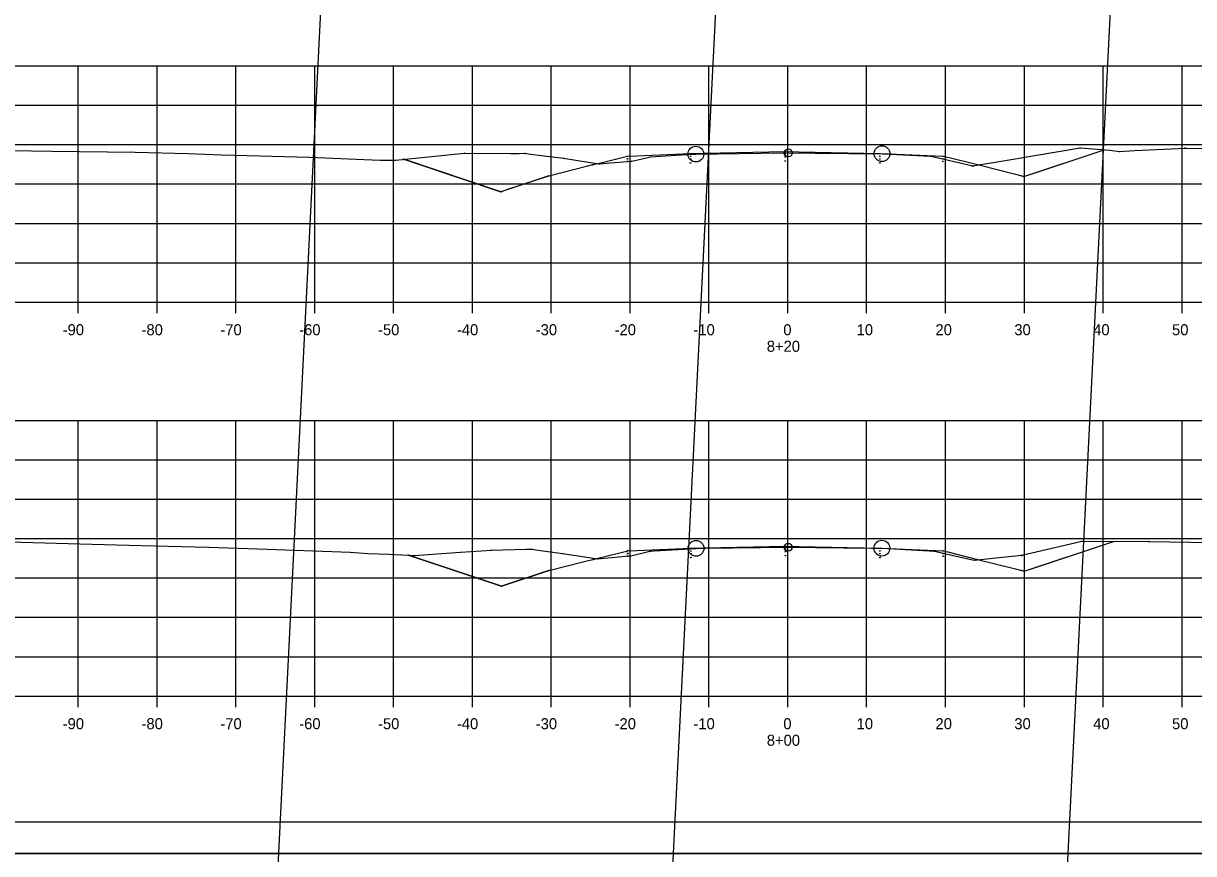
# Model space of a CAD drawing. Extents: x 1300404 to 1323571, y 234004 to 252077.
# Drawn here: x 1315620.3 to 1315768.7, y 242768.5 to 242873.8 of the extents above; entities that cross this region are included whole.
import ezdxf

# ---------------------------------------------------------------- set-up
doc = ezdxf.new("R2010")
doc.units = 0
for name, color, linetype in [('Default', 7, 'Continuous'), ('R_Axis', 7, 'Continuous'), ('R_Axis Annot', 7, 'Continuous'), ('R_Draft', 7, 'Continuous'), ('R_Exist Surface', 7, 'Continuous'), ('R_Fin Surface', 7, 'Continuous'), ('R_Floodway', 7, 'Continuous'), ('R_Grid', 7, 'Continuous'), ('R_No Plot', 7, 'Continuous')]:
    doc.layers.add(name, color=color, linetype=linetype)

msp = doc.modelspace()

# ---------------------------------------------------------------- linework, layer by layer
at = {"layer": 'Default'}
msp.add_line((1315875.46, 242772.46), (1315559.28, 242772.46), dxfattribs=at)
at = {"layer": 'R_Axis'}
for p, q in [((1315577.28, 242838.46), (1315857.28, 242838.46)), ((1315627.28, 242837.06), (1315627.28, 242838.46)), ((1315637.28, 242837.06), (1315637.28, 242838.46)), ((1315647.28, 242837.06), (1315647.28, 242838.46)), ((1315657.28, 242837.06), (1315657.28, 242838.46)), ((1315667.28, 242837.06), (1315667.28, 242838.46)), ((1315677.28, 242837.06), (1315677.28, 242838.46)), ((1315687.28, 242837.06), (1315687.28, 242838.46)), ((1315697.28, 242837.06), (1315697.28, 242838.46)), ((1315707.28, 242837.06), (1315707.28, 242838.46)), ((1315717.28, 242837.06), (1315717.28, 242838.46)), ((1315727.28, 242837.06), (1315727.28, 242838.46)), ((1315737.28, 242837.06), (1315737.28, 242838.46)), ((1315747.28, 242837.06), (1315747.28, 242838.46)), ((1315757.28, 242837.06), (1315757.28, 242838.46)), ((1315767.28, 242837.06), (1315767.28, 242838.46)), ((1315577.28, 242788.46), (1315857.28, 242788.46)), ((1315627.28, 242787.06), (1315627.28, 242788.46)), ((1315637.28, 242787.06), (1315637.28, 242788.46)), ((1315647.28, 242787.06), (1315647.28, 242788.46)), ((1315657.28, 242787.06), (1315657.28, 242788.46)), ((1315667.28, 242787.06), (1315667.28, 242788.46)), ((1315677.28, 242787.06), (1315677.28, 242788.46)), ((1315687.28, 242787.06), (1315687.28, 242788.46)), ((1315697.28, 242787.06), (1315697.28, 242788.46)), ((1315707.28, 242787.06), (1315707.28, 242788.46)), ((1315717.28, 242787.06), (1315717.28, 242788.46)), ((1315727.28, 242787.06), (1315727.28, 242788.46)), ((1315737.28, 242787.06), (1315737.28, 242788.46)), ((1315747.28, 242787.06), (1315747.28, 242788.46)), ((1315757.28, 242787.06), (1315757.28, 242788.46)), ((1315767.28, 242787.06), (1315767.28, 242788.46))]:
    msp.add_line(p, q, dxfattribs=at)
at = {"layer": 'R_Draft'}
for points in [[(1315754.35, 242858.09), (1315754.4, 242857.99), (1315754.3, 242857.99)], [(1315757.4, 242857.85), (1315757.45, 242857.75), (1315757.35, 242857.75)], [(1315757.4, 242857.85), (1315757.45, 242857.75), (1315757.35, 242857.75)], [(1315767.7, 242858.07), (1315767.75, 242857.97), (1315767.65, 242857.97)], [(1315667.52, 242856.53), (1315667.57, 242856.43), (1315667.47, 242856.43)], [(1315668.56, 242856.64), (1315668.61, 242856.54), (1315668.51, 242856.54)], [(1315668.56, 242856.64), (1315668.61, 242856.54), (1315668.51, 242856.54)], [(1315676.29, 242857.41), (1315676.34, 242857.31), (1315676.24, 242857.31)], [(1315683.92, 242857.4), (1315683.97, 242857.3), (1315683.87, 242857.3)], [(1315688.85, 242856.79), (1315688.9, 242856.69), (1315688.8, 242856.69)], [(1315696.95, 242857.05), (1315697, 242856.95), (1315696.9, 242856.95)], [(1315696.95, 242856.72), (1315697, 242856.62), (1315696.9, 242856.62)], [(1315696.95, 242856.39), (1315697, 242856.29), (1315696.9, 242856.29)], [(1315697.48, 242856.4), (1315697.53, 242856.3), (1315697.43, 242856.3)], [(1315699.86, 242856.96), (1315699.91, 242856.86), (1315699.81, 242856.86)], [(1315704.95, 242857.37), (1315705, 242857.27), (1315704.9, 242857.27)], [(1315704.95, 242857.04), (1315705, 242856.94), (1315704.9, 242856.94)], [(1315704.95, 242856.71), (1315705, 242856.61), (1315704.9, 242856.61)], [(1315716.95, 242857.61), (1315717, 242857.51), (1315716.9, 242857.51)], [(1315716.95, 242857.28), (1315717, 242857.18), (1315716.9, 242857.18)], [(1315716.95, 242856.95), (1315717, 242856.85), (1315716.9, 242856.85)], [(1315716.95, 242856.45), (1315717, 242856.35), (1315716.9, 242856.35)], [(1315728.95, 242857.37), (1315729, 242857.27), (1315728.9, 242857.27)], [(1315728.95, 242857.04), (1315729, 242856.94), (1315728.9, 242856.94)], [(1315728.95, 242856.71), (1315729, 242856.61), (1315728.9, 242856.61)], [(1315735.38, 242857.04), (1315735.43, 242856.94), (1315735.33, 242856.94)], [(1315736.95, 242857.05), (1315737, 242856.95), (1315736.9, 242856.95)], [(1315736.95, 242856.72), (1315737, 242856.62), (1315736.9, 242856.62)], [(1315736.95, 242856.39), (1315737, 242856.29), (1315736.9, 242856.29)], [(1315759.35, 242857.65), (1315759.4, 242857.55), (1315759.3, 242857.55)], [(1315692.57, 242855.96), (1315692.62, 242855.86), (1315692.52, 242855.86)], [(1315693.38, 242856.07), (1315693.43, 242855.97), (1315693.33, 242855.97)], [(1315704.95, 242856.21), (1315705, 242856.11), (1315704.9, 242856.11)], [(1315728.95, 242856.21), (1315729, 242856.11), (1315728.9, 242856.11)], [(1315740.76, 242855.79), (1315740.81, 242855.69), (1315740.71, 242855.69)], [(1315741.33, 242855.96), (1315741.38, 242855.86), (1315741.28, 242855.86)], [(1315686.95, 242854.55), (1315687, 242854.45), (1315686.9, 242854.45)], [(1315746.95, 242854.55), (1315747, 242854.45), (1315746.9, 242854.45)], [(1315747.23, 242854.46), (1315747.28, 242854.36), (1315747.18, 242854.36)], [(1315680.88, 242852.53), (1315680.93, 242852.43), (1315680.83, 242852.43)], [(1315716.97, 242807.53), (1315717.02, 242807.43), (1315716.92, 242807.43)], [(1315754.58, 242808.18), (1315754.63, 242808.08), (1315754.53, 242808.08)], [(1315758.47, 242808.11), (1315758.52, 242808.01), (1315758.42, 242808.01)], [(1315758.47, 242808.11), (1315758.52, 242808.01), (1315758.42, 242808.01)], [(1315763.05, 242808.13), (1315763.1, 242808.03), (1315763, 242808.03)], [(1315669.15, 242806.41), (1315669.2, 242806.31), (1315669.1, 242806.31)], [(1315669.15, 242806.41), (1315669.2, 242806.31), (1315669.1, 242806.31)], [(1315669.91, 242806.35), (1315669.96, 242806.25), (1315669.86, 242806.25)], [(1315679.7, 242807.05), (1315679.75, 242806.95), (1315679.65, 242806.95)], [(1315684.75, 242807.16), (1315684.8, 242807.06), (1315684.7, 242807.06)], [(1315688.7, 242806.6), (1315688.75, 242806.5), (1315688.65, 242806.5)], [(1315692.59, 242805.87), (1315692.64, 242805.77), (1315692.54, 242805.77)], [(1315693.13, 242805.94), (1315693.18, 242805.84), (1315693.08, 242805.84)], [(1315696.97, 242806.97), (1315697.02, 242806.87), (1315696.92, 242806.87)], [(1315696.97, 242806.63), (1315697.02, 242806.53), (1315696.92, 242806.53)], [(1315696.97, 242806.3), (1315697.02, 242806.2), (1315696.92, 242806.2)], [(1315697.36, 242806.31), (1315697.41, 242806.21), (1315697.31, 242806.21)], [(1315699.82, 242806.91), (1315699.87, 242806.81), (1315699.77, 242806.81)], [(1315704.97, 242807.29), (1315705.02, 242807.19), (1315704.92, 242807.19)], [(1315704.97, 242806.95), (1315705.02, 242806.85), (1315704.92, 242806.85)], [(1315704.97, 242806.62), (1315705.02, 242806.52), (1315704.92, 242806.52)], [(1315704.97, 242806.12), (1315705.02, 242806.02), (1315704.92, 242806.02)], [(1315716.97, 242807.19), (1315717.02, 242807.09), (1315716.92, 242807.09)], [(1315716.97, 242806.86), (1315717.02, 242806.76), (1315716.92, 242806.76)], [(1315716.97, 242806.36), (1315717.02, 242806.26), (1315716.92, 242806.26)], [(1315728.97, 242807.29), (1315729.02, 242807.19), (1315728.92, 242807.19)], [(1315728.97, 242806.95), (1315729.02, 242806.85), (1315728.92, 242806.85)], [(1315728.97, 242806.62), (1315729.02, 242806.52), (1315728.92, 242806.52)], [(1315728.97, 242806.12), (1315729.02, 242806.02), (1315728.92, 242806.02)], [(1315735.87, 242806.92), (1315735.92, 242806.82), (1315735.82, 242806.82)], [(1315736.97, 242806.97), (1315737.02, 242806.87), (1315736.92, 242806.87)], [(1315736.97, 242806.63), (1315737.02, 242806.53), (1315736.92, 242806.53)], [(1315736.97, 242806.3), (1315737.02, 242806.2), (1315736.92, 242806.2)], [(1315741.34, 242805.87), (1315741.39, 242805.77), (1315741.29, 242805.77)], [(1315746.94, 242806.38), (1315746.99, 242806.28), (1315746.89, 242806.28)], [(1315686.97, 242804.47), (1315687.02, 242804.37), (1315686.92, 242804.37)], [(1315740.95, 242805.77), (1315741, 242805.67), (1315740.9, 242805.67)], [(1315746.97, 242804.47), (1315747.02, 242804.37), (1315746.92, 242804.37)], [(1315747.25, 242804.37), (1315747.3, 242804.27), (1315747.2, 242804.27)], [(1315680.98, 242802.47), (1315681.03, 242802.37), (1315680.93, 242802.37)]]:
    msp.add_lwpolyline(points, close=True, dxfattribs=at)
at = {"layer": 'R_Exist Surface'}
for points in [[(1315613.53, 242857.78), (1315623.94, 242857.62), (1315634.52, 242857.51), (1315641.22, 242857.32), (1315645.46, 242857.17), (1315656.64, 242856.87), (1315663.51, 242856.55), (1315665.61, 242856.47), (1315667.52, 242856.48), (1315675.43, 242857.3), (1315676.29, 242857.36), (1315682.09, 242857.34), (1315683.2, 242857.34), (1315683.92, 242857.35), (1315684.63, 242857.25), (1315688.85, 242856.74), (1315691.96, 242856.24), (1315693.38, 242856.02), (1315694.8, 242856.14), (1315697.48, 242856.35), (1315698.24, 242856.53), (1315699.86, 242856.91), (1315703.78, 242857.14), (1315705.61, 242857.25), (1315713.9, 242857.36), (1315717.33, 242857.4), (1315720.76, 242857.37), (1315729.23, 242857.3), (1315731.12, 242857.2), (1315735.38, 242856.99), (1315737.1, 242856.59), (1315740.76, 242855.74), (1315745.61, 242856.57), (1315754.35, 242858.04), (1315758.11, 242857.73), (1315759.35, 242857.6), (1315761.29, 242857.69), (1315767.7, 242858.02), (1315774.57, 242857.98)], [(1315617.04, 242808.07), (1315627.49, 242807.79), (1315635.25, 242807.59), (1315643.84, 242807.36), (1315651.26, 242807.09), (1315661.78, 242806.72), (1315664, 242806.54), (1315666.69, 242806.48), (1315669.91, 242806.3), (1315675.77, 242806.71), (1315679.7, 242807), (1315684.07, 242807.1), (1315684.75, 242807.11), (1315685.62, 242807), (1315688.7, 242806.55), (1315691.25, 242806.16), (1315693.13, 242805.89), (1315696.7, 242806.21), (1315697.36, 242806.26), (1315699.61, 242806.81), (1315699.82, 242806.86), (1315700.32, 242806.89), (1315705.64, 242807.21), (1315706.84, 242807.23), (1315717.32, 242807.35), (1315727.86, 242807.25), (1315729.21, 242807.24), (1315735.19, 242806.91), (1315735.87, 242806.87), (1315740.51, 242805.82), (1315740.95, 242805.72), (1315743.3, 242805.96), (1315746.94, 242806.33), (1315751.88, 242807.5), (1315754.58, 242808.13), (1315754.85, 242808.1), (1315755.67, 242808.13), (1315763.05, 242808.08), (1315779.03, 242807.85)]]:
    msp.add_lwpolyline(points, dxfattribs=at)
at = {"layer": 'R_Fin Surface'}
for points in [[(1315668.56, 242856.59), (1315670.42, 242855.97), (1315680.88, 242852.48), (1315681.78, 242852.78), (1315686.95, 242854.5), (1315691.75, 242855.7), (1315692.57, 242855.91), (1315693.21, 242856.07), (1315696.95, 242857), (1315698.12, 242857.05), (1315704.95, 242857.32), (1315706.69, 242857.36), (1315716.95, 242857.56), (1315718.68, 242857.53), (1315728.95, 242857.32), (1315730.09, 242857.28), (1315736.95, 242857), (1315737.57, 242856.85), (1315741.33, 242855.91), (1315746.15, 242854.7), (1315746.95, 242854.5), (1315746.99, 242854.49), (1315747.23, 242854.41), (1315748.67, 242854.89), (1315757.4, 242857.8)], [(1315669.15, 242806.36), (1315670.94, 242805.77), (1315680.98, 242802.42), (1315681.87, 242802.72), (1315686.97, 242804.42), (1315691.77, 242805.62), (1315692.59, 242805.82), (1315693.23, 242805.98), (1315696.97, 242806.92), (1315698.13, 242806.96), (1315704.97, 242807.24), (1315706.71, 242807.27), (1315716.97, 242807.48), (1315718.7, 242807.44), (1315728.97, 242807.24), (1315730.11, 242807.19), (1315736.97, 242806.92), (1315737.59, 242806.76), (1315741.34, 242805.82), (1315746.17, 242804.62), (1315746.97, 242804.42), (1315747.01, 242804.4), (1315747.25, 242804.32), (1315748.7, 242804.8), (1315758.47, 242808.06)]]:
    msp.add_lwpolyline(points, dxfattribs=at)
at = {"layer": 'R_Floodway'}
for p, q in [((1315724.08, 242194.52), (1315766.53, 243041.85)), ((1315673.23, 242178.64), (1315715.45, 243021.54)), ((1315622.37, 242162.75), (1315664.37, 243001.24))]:
    msp.add_line(p, q, dxfattribs=at)
at = {"layer": 'R_Grid'}
for p, q in [((1315577.28, 242868.46), (1315857.28, 242868.46)), ((1315627.28, 242838.46), (1315627.28, 242868.46)), ((1315637.28, 242838.46), (1315637.28, 242868.46)), ((1315647.28, 242838.46), (1315647.28, 242868.46)), ((1315657.28, 242838.46), (1315657.28, 242868.46)), ((1315667.28, 242838.46), (1315667.28, 242868.46)), ((1315677.28, 242838.46), (1315677.28, 242868.46)), ((1315687.28, 242838.46), (1315687.28, 242868.46)), ((1315697.28, 242838.46), (1315697.28, 242868.46)), ((1315707.28, 242838.46), (1315707.28, 242868.46)), ((1315717.28, 242838.46), (1315717.28, 242868.46)), ((1315727.28, 242838.46), (1315727.28, 242868.46)), ((1315737.28, 242838.46), (1315737.28, 242868.46)), ((1315747.28, 242838.46), (1315747.28, 242868.46)), ((1315757.28, 242838.46), (1315757.28, 242868.46)), ((1315767.28, 242838.46), (1315767.28, 242868.46)), ((1315577.28, 242863.46), (1315857.28, 242863.46)), ((1315577.28, 242858.46), (1315857.28, 242858.46)), ((1315577.28, 242853.46), (1315857.28, 242853.46)), ((1315577.28, 242848.46), (1315857.28, 242848.46)), ((1315577.28, 242843.46), (1315857.28, 242843.46)), ((1315577.28, 242838.46), (1315857.28, 242838.46)), ((1315577.28, 242823.46), (1315857.28, 242823.46)), ((1315627.28, 242788.46), (1315627.28, 242823.46)), ((1315637.28, 242788.46), (1315637.28, 242823.46)), ((1315647.28, 242788.46), (1315647.28, 242823.46)), ((1315657.28, 242788.46), (1315657.28, 242823.46)), ((1315667.28, 242788.46), (1315667.28, 242823.46)), ((1315677.28, 242788.46), (1315677.28, 242823.46)), ((1315687.28, 242788.46), (1315687.28, 242823.46)), ((1315697.28, 242788.46), (1315697.28, 242823.46)), ((1315707.28, 242788.46), (1315707.28, 242823.46)), ((1315717.28, 242788.46), (1315717.28, 242823.46)), ((1315727.28, 242788.46), (1315727.28, 242823.46)), ((1315737.28, 242788.46), (1315737.28, 242823.46)), ((1315747.28, 242788.46), (1315747.28, 242823.46)), ((1315757.28, 242788.46), (1315757.28, 242823.46)), ((1315767.28, 242788.46), (1315767.28, 242823.46)), ((1315577.28, 242818.46), (1315857.28, 242818.46)), ((1315577.28, 242813.46), (1315857.28, 242813.46)), ((1315577.28, 242808.46), (1315857.28, 242808.46)), ((1315577.28, 242803.46), (1315857.28, 242803.46)), ((1315577.28, 242798.46), (1315857.28, 242798.46)), ((1315577.28, 242793.46), (1315857.28, 242793.46)), ((1315577.28, 242788.46), (1315857.28, 242788.46))]:
    msp.add_line(p, q, dxfattribs=at)
at = {"layer": 'R_No Plot'}
msp.add_line((1315546.87, 242768.48), (1315880.21, 242768.48), dxfattribs=at)
for points in [[(1315546.87, 242981.81), (1315880.21, 242981.81), (1315880.21, 242768.47), (1315546.87, 242768.47)], [(1315793.2, 242977.92), (1315793.2, 242968.04), (1315828.93, 242968.04), (1315828.93, 242965.12), (1315852.13, 242965.12), (1315852.13, 242943), (1315875.46, 242943), (1315875.46, 242772.46), (1315559.28, 242772.46), (1315559.28, 242977.92)]]:
    msp.add_lwpolyline(points, close=True, dxfattribs=at)
for points in [[(1315680.88, 242852.48), (1315668.56, 242856.59)], [(1315686.95, 242854.5), (1315680.88, 242852.48), (1315668.56, 242856.59)], [(1315686.95, 242854.5), (1315680.88, 242852.48), (1315668.56, 242856.59)], [(1315686.95, 242854.5), (1315680.88, 242852.48), (1315668.56, 242856.59)], [(1315686.95, 242854.5), (1315680.88, 242852.48), (1315668.56, 242856.59)], [(1315686.95, 242854.5), (1315680.88, 242852.48), (1315668.56, 242856.59)], [(1315746.95, 242854.5), (1315747.23, 242854.41), (1315757.4, 242857.8)], [(1315746.95, 242854.5), (1315747.23, 242854.41), (1315757.4, 242857.8)], [(1315746.95, 242854.5), (1315747.23, 242854.41), (1315757.4, 242857.8)], [(1315746.95, 242854.5), (1315747.23, 242854.41), (1315757.4, 242857.8)], [(1315746.97, 242804.42), (1315747.25, 242804.32), (1315758.47, 242808.06)], [(1315746.97, 242804.42), (1315747.25, 242804.32), (1315758.47, 242808.06)], [(1315746.97, 242804.42), (1315747.25, 242804.32), (1315758.47, 242808.06)], [(1315746.97, 242804.42), (1315747.25, 242804.32), (1315758.47, 242808.06)], [(1315680.98, 242802.42), (1315669.15, 242806.36)], [(1315686.97, 242804.42), (1315680.98, 242802.42), (1315669.15, 242806.36)], [(1315686.97, 242804.42), (1315680.98, 242802.42), (1315669.15, 242806.36)], [(1315686.97, 242804.42), (1315680.98, 242802.42), (1315669.15, 242806.36)], [(1315686.97, 242804.42), (1315680.98, 242802.42), (1315669.15, 242806.36)], [(1315686.97, 242804.42), (1315680.98, 242802.42), (1315669.15, 242806.36)]]:
    msp.add_lwpolyline(points, dxfattribs=at)
for centre, radius in [((1315705.61, 242857.25), 1), ((1315717.33, 242857.4), 0.5), ((1315729.23, 242857.3), 1), ((1315705.64, 242807.21), 1), ((1315717.32, 242807.35), 0.5), ((1315729.21, 242807.24), 1)]:
    msp.add_circle(centre, radius, dxfattribs=at)

# ---------------------------------------------------------------- texts
at = {"layer": 'R_Axis Annot'}
for s, p in [('-90', (1315625.31, 242834.26)), ('-80', (1315635.31, 242834.26)), ('-70', (1315645.31, 242834.26)), ('-60', (1315655.31, 242834.26)), ('-50', (1315665.31, 242834.26)), ('-40', (1315675.31, 242834.26)), ('-30', (1315685.31, 242834.26)), ('-20', (1315695.31, 242834.26)), ('-10', (1315705.31, 242834.26)), ('0', (1315716.71, 242834.26)), ('10', (1315726.01, 242834.26)), ('20', (1315736.01, 242834.26)), ('30', (1315746.01, 242834.26)), ('40', (1315756.01, 242834.26)), ('50', (1315766.01, 242834.26)), ('8+20', (1315714.61, 242832.16)), ('-90', (1315625.31, 242784.26)), ('-80', (1315635.31, 242784.26)), ('-70', (1315645.31, 242784.26)), ('-60', (1315655.31, 242784.26)), ('-50', (1315665.31, 242784.26)), ('-40', (1315675.31, 242784.26)), ('-30', (1315685.31, 242784.26)), ('-20', (1315695.31, 242784.26)), ('-10', (1315705.31, 242784.26)), ('0', (1315716.71, 242784.26)), ('10', (1315726.01, 242784.26)), ('20', (1315736.01, 242784.26)), ('30', (1315746.01, 242784.26)), ('40', (1315756.01, 242784.26)), ('50', (1315766.01, 242784.26)), ('8+00', (1315714.61, 242782.16))]:
    msp.add_text(s, height=1.4, dxfattribs=at).set_placement(p)

doc.saveas('drawing.dxf')
